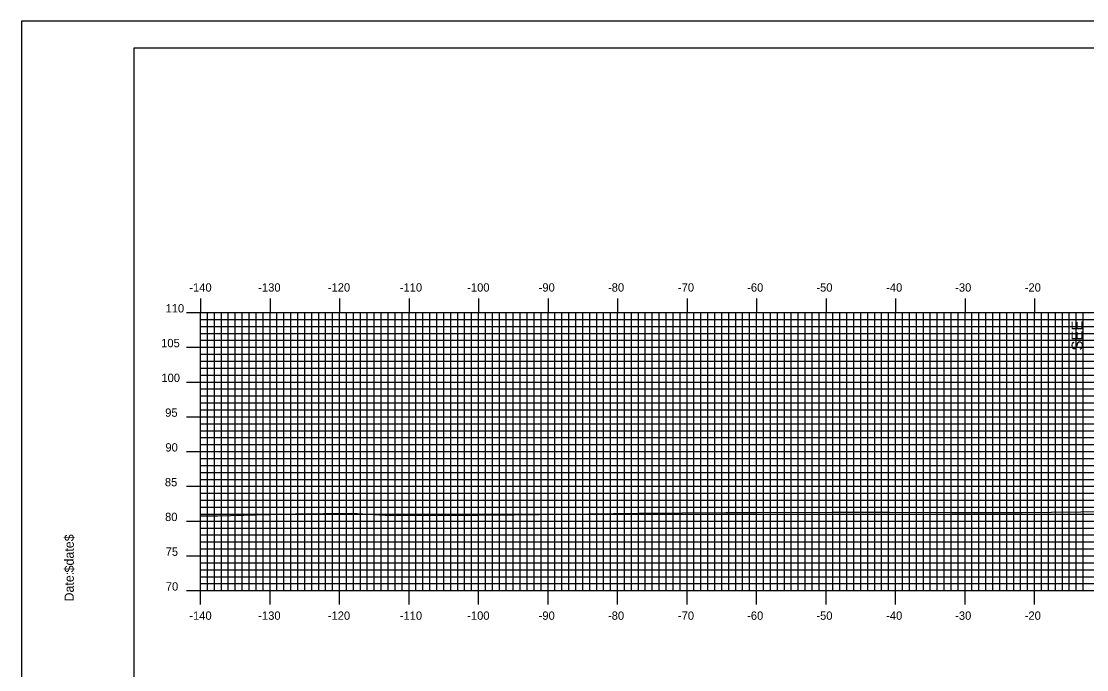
# Model space of a CAD drawing. Extents: x 2846 to 3190, y -1658 to -1438.
# Drawn here: x 2846.4 to 2999.7, y -1531 to -1437.7 of the extents above; entities that cross this region are included whole.
import ezdxf

# ---------------------------------------------------------------- set-up
doc = ezdxf.new("R2010")
doc.units = 0
for name, color, linetype in [('ANNOTATION', 7, 'Continuous'), ('BORDER', 7, 'Continuous'), ('H_V ANNOTATION', 7, 'Continuous'), ('MAJOR', 7, 'Continuous'), ('MINOR', 7, 'Continuous'), ('PLOT BOUNDARY', 7, 'Continuous'), ('S_Roadway_Centerline', 7, 'Continuous')]:
    doc.layers.add(name, color=color, linetype=linetype)

msp = doc.modelspace()

# ---------------------------------------------------------------- linework, layer by layer
at = {"layer": 'BORDER'}
msp.add_lwpolyline([(2862.61, -1651.6), (3182.61, -1651.6), (3182.61, -1441.6), (2862.61, -1441.6)], close=True, dxfattribs=at)
at = {"layer": 'MAJOR'}
for p, q in [((2872.21, -1477.6), (2872.21, -1479.6)), ((2882.21, -1477.6), (2882.21, -1479.6)), ((2892.21, -1477.6), (2892.21, -1479.6)), ((2902.21, -1477.6), (2902.21, -1479.6)), ((2912.21, -1477.6), (2912.21, -1479.6)), ((2922.21, -1477.6), (2922.21, -1479.6)), ((2932.21, -1477.6), (2932.21, -1479.6)), ((2942.21, -1477.6), (2942.21, -1479.6)), ((2952.21, -1477.6), (2952.21, -1479.6)), ((2962.21, -1477.6), (2962.21, -1479.6)), ((2972.21, -1477.6), (2972.21, -1479.6)), ((2982.21, -1477.6), (2982.21, -1479.6)), ((2992.21, -1477.6), (2992.21, -1479.6)), ((2870.21, -1479.6), (2872.21, -1479.6)), ((2872.21, -1479.6), (3152.21, -1479.6)), ((2872.21, -1519.6), (2872.21, -1479.6)), ((2872.21, -1519.6), (2872.21, -1479.6)), ((2872.21, -1479.6), (3152.21, -1479.6)), ((2882.21, -1519.6), (2882.21, -1479.6)), ((2892.21, -1519.6), (2892.21, -1479.6)), ((2902.21, -1519.6), (2902.21, -1479.6)), ((2912.21, -1519.6), (2912.21, -1479.6)), ((2922.21, -1519.6), (2922.21, -1479.6)), ((2932.21, -1519.6), (2932.21, -1479.6)), ((2942.21, -1519.6), (2942.21, -1479.6)), ((2952.21, -1519.6), (2952.21, -1479.6)), ((2962.21, -1519.6), (2962.21, -1479.6)), ((2972.21, -1519.6), (2972.21, -1479.6)), ((2982.21, -1519.6), (2982.21, -1479.6)), ((2992.21, -1519.6), (2992.21, -1479.6)), ((2870.21, -1484.6), (2872.21, -1484.6)), ((2872.21, -1484.6), (3152.21, -1484.6)), ((2870.21, -1489.6), (2872.21, -1489.6)), ((2872.21, -1489.6), (3152.21, -1489.6)), ((2870.21, -1494.6), (2872.21, -1494.6)), ((2872.21, -1494.6), (3152.21, -1494.6)), ((2870.21, -1499.6), (2872.21, -1499.6)), ((2872.21, -1499.6), (3152.21, -1499.6)), ((2870.21, -1504.6), (2872.21, -1504.6)), ((2872.21, -1504.6), (3152.21, -1504.6)), ((2870.21, -1509.6), (2872.21, -1509.6)), ((2872.21, -1509.6), (3152.21, -1509.6)), ((2870.21, -1514.6), (2872.21, -1514.6)), ((2872.21, -1514.6), (3152.21, -1514.6)), ((2870.21, -1519.6), (2872.21, -1519.6)), ((2872.21, -1519.6), (3152.21, -1519.6)), ((2872.21, -1519.6), (3152.21, -1519.6)), ((2872.21, -1521.61), (2872.21, -1519.6)), ((2882.21, -1521.61), (2882.21, -1519.6)), ((2892.21, -1521.61), (2892.21, -1519.6)), ((2902.21, -1521.61), (2902.21, -1519.6)), ((2912.21, -1521.61), (2912.21, -1519.6)), ((2922.21, -1521.61), (2922.21, -1519.6)), ((2932.21, -1521.61), (2932.21, -1519.6)), ((2942.21, -1521.61), (2942.21, -1519.6)), ((2952.21, -1521.61), (2952.21, -1519.6)), ((2962.21, -1521.61), (2962.21, -1519.6)), ((2972.21, -1521.61), (2972.21, -1519.6)), ((2982.21, -1521.61), (2982.21, -1519.6)), ((2992.21, -1521.61), (2992.21, -1519.6))]:
    msp.add_line(p, q, dxfattribs=at)
at = {"layer": 'MINOR'}
for p, q in [((2872.21, -1480.6), (3152.21, -1480.6)), ((2872.21, -1480.6), (2874.22, -1480.6)), ((2873.21, -1519.6), (2873.21, -1479.6)), ((2874.21, -1519.6), (2874.21, -1479.6)), ((2875.21, -1519.6), (2875.21, -1479.6)), ((2876.21, -1519.6), (2876.21, -1479.6)), ((2877.21, -1519.6), (2877.21, -1479.6)), ((2878.21, -1519.6), (2878.21, -1479.6)), ((2879.21, -1519.6), (2879.21, -1479.6)), ((2880.21, -1519.6), (2880.21, -1479.6)), ((2881.21, -1519.6), (2881.21, -1479.6)), ((2883.21, -1519.6), (2883.21, -1479.6)), ((2884.21, -1519.6), (2884.21, -1479.6)), ((2885.21, -1519.6), (2885.21, -1479.6)), ((2886.21, -1519.6), (2886.21, -1479.6)), ((2887.21, -1519.6), (2887.21, -1479.6)), ((2888.21, -1519.6), (2888.21, -1479.6)), ((2889.21, -1519.6), (2889.21, -1479.6)), ((2890.21, -1519.6), (2890.21, -1479.6)), ((2891.21, -1519.6), (2891.21, -1479.6)), ((2893.21, -1519.6), (2893.21, -1479.6)), ((2894.21, -1519.6), (2894.21, -1479.6)), ((2895.21, -1519.6), (2895.21, -1479.6)), ((2896.21, -1519.6), (2896.21, -1479.6)), ((2897.21, -1519.6), (2897.21, -1479.6)), ((2898.21, -1519.6), (2898.21, -1479.6)), ((2899.21, -1519.6), (2899.21, -1479.6)), ((2900.21, -1519.6), (2900.21, -1479.6)), ((2901.21, -1519.6), (2901.21, -1479.6)), ((2903.21, -1519.6), (2903.21, -1479.6)), ((2904.21, -1519.6), (2904.21, -1479.6)), ((2905.21, -1519.6), (2905.21, -1479.6)), ((2906.21, -1519.6), (2906.21, -1479.6)), ((2907.21, -1519.6), (2907.21, -1479.6)), ((2908.21, -1519.6), (2908.21, -1479.6)), ((2909.21, -1519.6), (2909.21, -1479.6)), ((2910.21, -1519.6), (2910.21, -1479.6)), ((2911.21, -1519.6), (2911.21, -1479.6)), ((2913.21, -1519.6), (2913.21, -1479.6)), ((2914.21, -1519.6), (2914.21, -1479.6)), ((2915.21, -1519.6), (2915.21, -1479.6)), ((2916.21, -1519.6), (2916.21, -1479.6)), ((2917.21, -1519.6), (2917.21, -1479.6)), ((2918.21, -1519.6), (2918.21, -1479.6)), ((2919.21, -1519.6), (2919.21, -1479.6)), ((2920.21, -1519.6), (2920.21, -1479.6)), ((2921.21, -1519.6), (2921.21, -1479.6)), ((2923.21, -1519.6), (2923.21, -1479.6)), ((2924.21, -1519.6), (2924.21, -1479.6)), ((2925.21, -1519.6), (2925.21, -1479.6)), ((2926.21, -1519.6), (2926.21, -1479.6)), ((2927.21, -1519.6), (2927.21, -1479.6)), ((2928.21, -1519.6), (2928.21, -1479.6)), ((2929.21, -1519.6), (2929.21, -1479.6)), ((2930.21, -1519.6), (2930.21, -1479.6)), ((2931.21, -1519.6), (2931.21, -1479.6)), ((2933.21, -1519.6), (2933.21, -1479.6)), ((2934.21, -1519.6), (2934.21, -1479.6)), ((2935.21, -1519.6), (2935.21, -1479.6)), ((2936.21, -1519.6), (2936.21, -1479.6)), ((2937.21, -1519.6), (2937.21, -1479.6)), ((2938.21, -1519.6), (2938.21, -1479.6)), ((2939.21, -1519.6), (2939.21, -1479.6)), ((2940.21, -1519.6), (2940.21, -1479.6)), ((2941.21, -1519.6), (2941.21, -1479.6)), ((2943.21, -1519.6), (2943.21, -1479.6)), ((2944.21, -1519.6), (2944.21, -1479.6)), ((2945.21, -1519.6), (2945.21, -1479.6)), ((2946.21, -1519.6), (2946.21, -1479.6)), ((2947.21, -1519.6), (2947.21, -1479.6)), ((2948.21, -1519.6), (2948.21, -1479.6)), ((2949.21, -1519.6), (2949.21, -1479.6)), ((2950.21, -1519.6), (2950.21, -1479.6)), ((2951.21, -1519.6), (2951.21, -1479.6)), ((2953.21, -1519.6), (2953.21, -1479.6)), ((2954.21, -1519.6), (2954.21, -1479.6)), ((2955.21, -1519.6), (2955.21, -1479.6)), ((2956.21, -1519.6), (2956.21, -1479.6)), ((2957.21, -1519.6), (2957.21, -1479.6)), ((2958.21, -1519.6), (2958.21, -1479.6)), ((2959.21, -1519.6), (2959.21, -1479.6)), ((2960.21, -1519.6), (2960.21, -1479.6)), ((2961.21, -1519.6), (2961.21, -1479.6)), ((2963.21, -1519.6), (2963.21, -1479.6)), ((2964.21, -1519.6), (2964.21, -1479.6)), ((2965.21, -1519.6), (2965.21, -1479.6)), ((2966.21, -1519.6), (2966.21, -1479.6)), ((2967.21, -1519.6), (2967.21, -1479.6)), ((2968.21, -1519.6), (2968.21, -1479.6)), ((2969.21, -1519.6), (2969.21, -1479.6)), ((2970.21, -1519.6), (2970.21, -1479.6)), ((2971.21, -1519.6), (2971.21, -1479.6)), ((2973.21, -1519.6), (2973.21, -1479.6)), ((2974.21, -1519.6), (2974.21, -1479.6)), ((2975.21, -1519.6), (2975.21, -1479.6)), ((2976.21, -1519.6), (2976.21, -1479.6)), ((2977.21, -1519.6), (2977.21, -1479.6)), ((2978.21, -1519.6), (2978.21, -1479.6)), ((2979.21, -1519.6), (2979.21, -1479.6)), ((2980.21, -1519.6), (2980.21, -1479.6)), ((2981.21, -1519.6), (2981.21, -1479.6)), ((2983.21, -1519.6), (2983.21, -1479.6)), ((2984.21, -1519.6), (2984.21, -1479.6)), ((2985.21, -1519.6), (2985.21, -1479.6)), ((2986.21, -1519.6), (2986.21, -1479.6)), ((2987.21, -1519.6), (2987.21, -1479.6)), ((2988.21, -1519.6), (2988.21, -1479.6)), ((2989.21, -1519.6), (2989.21, -1479.6)), ((2990.21, -1519.6), (2990.21, -1479.6)), ((2991.21, -1519.6), (2991.21, -1479.6)), ((2993.21, -1519.6), (2993.21, -1479.6)), ((2994.21, -1519.6), (2994.21, -1479.6)), ((2995.21, -1519.6), (2995.21, -1479.6)), ((2996.21, -1519.6), (2996.21, -1479.6)), ((2997.21, -1519.6), (2997.21, -1479.6)), ((2998.21, -1519.6), (2998.21, -1479.6)), ((2999.21, -1519.6), (2999.21, -1479.6)), ((2872.21, -1481.6), (3152.21, -1481.6)), ((2872.21, -1481.6), (2874.22, -1481.6)), ((2872.21, -1482.6), (3152.21, -1482.6)), ((2872.21, -1482.6), (2874.22, -1482.6)), ((2872.21, -1483.6), (3152.21, -1483.6)), ((2872.21, -1483.6), (2874.22, -1483.6)), ((2872.21, -1485.6), (3152.21, -1485.6)), ((2872.21, -1485.6), (2874.22, -1485.6)), ((2872.21, -1486.6), (3152.21, -1486.6)), ((2872.21, -1486.6), (2874.22, -1486.6)), ((2872.21, -1487.6), (3152.21, -1487.6)), ((2872.21, -1487.6), (2874.22, -1487.6)), ((2872.21, -1488.6), (3152.21, -1488.6)), ((2872.21, -1488.6), (2874.22, -1488.6)), ((2872.21, -1490.6), (3152.21, -1490.6)), ((2872.21, -1490.6), (2874.22, -1490.6)), ((2872.21, -1491.6), (3152.21, -1491.6)), ((2872.21, -1491.6), (2874.22, -1491.6)), ((2872.21, -1492.6), (3152.21, -1492.6)), ((2872.21, -1492.6), (2874.22, -1492.6)), ((2872.21, -1493.6), (3152.21, -1493.6)), ((2872.21, -1493.6), (2874.22, -1493.6)), ((2872.21, -1495.6), (3152.21, -1495.6)), ((2872.21, -1495.6), (2874.22, -1495.6)), ((2872.21, -1496.6), (3152.21, -1496.6)), ((2872.21, -1496.6), (2874.22, -1496.6)), ((2872.21, -1497.6), (3152.21, -1497.6)), ((2872.21, -1497.6), (2874.22, -1497.6)), ((2872.21, -1498.6), (3152.21, -1498.6)), ((2872.21, -1498.6), (2874.22, -1498.6)), ((2872.21, -1500.6), (3152.21, -1500.6)), ((2872.21, -1500.6), (2874.22, -1500.6)), ((2872.21, -1501.6), (3152.21, -1501.6)), ((2872.21, -1501.6), (2874.22, -1501.6)), ((2872.21, -1502.6), (3152.21, -1502.6)), ((2872.21, -1502.6), (2874.22, -1502.6)), ((2872.21, -1503.6), (3152.21, -1503.6)), ((2872.21, -1503.6), (2874.22, -1503.6)), ((2872.21, -1505.6), (3152.21, -1505.6)), ((2872.21, -1505.6), (2874.22, -1505.6)), ((2872.21, -1506.6), (3152.21, -1506.6)), ((2872.21, -1506.6), (2874.22, -1506.6)), ((2872.21, -1507.6), (3152.21, -1507.6)), ((2872.21, -1507.6), (2874.22, -1507.6)), ((2872.21, -1508.6), (3152.21, -1508.6)), ((2872.21, -1508.6), (2874.22, -1508.6)), ((2872.21, -1510.6), (3152.21, -1510.6)), ((2872.21, -1510.6), (2874.22, -1510.6)), ((2872.21, -1511.6), (3152.21, -1511.6)), ((2872.21, -1511.6), (2874.22, -1511.6)), ((2872.21, -1512.6), (3152.21, -1512.6)), ((2872.21, -1512.6), (2874.22, -1512.6)), ((2872.21, -1513.6), (3152.21, -1513.6)), ((2872.21, -1513.6), (2874.22, -1513.6)), ((2872.21, -1515.6), (3152.21, -1515.6)), ((2872.21, -1515.6), (2874.22, -1515.6)), ((2872.21, -1516.6), (3152.21, -1516.6)), ((2872.21, -1516.6), (2874.22, -1516.6)), ((2872.21, -1517.6), (3152.21, -1517.6)), ((2872.21, -1517.6), (2874.22, -1517.6)), ((2872.21, -1518.6), (3152.21, -1518.6)), ((2872.21, -1518.6), (2874.22, -1518.6))]:
    msp.add_line(p, q, dxfattribs=at)
at = {"layer": 'PLOT BOUNDARY'}
msp.add_lwpolyline([(2846.43, -1657.72), (3186.43, -1657.72), (3186.43, -1437.72), (2846.43, -1437.72)], close=True, dxfattribs=at)
at = {"layer": 'S_Roadway_Centerline'}
msp.add_lwpolyline([(2872.21, -1508.85), (2874.71, -1508.85), (2885.9, -1508.57), (2893.94, -1508.45), (2899.61, -1508.81), (2912.04, -1508.73), (2917.35, -1508.68), (2935.24, -1508.46), (2947.81, -1508.37), (2952.31, -1508.37), (2963.28, -1508.33), (2971.32, -1508.33), (2980.37, -1508.35), (2990.42, -1508.38), (2998.86, -1508.25), (3009.93, -1508.16)], dxfattribs=at)

# ---------------------------------------------------------------- texts
at = {"layer": 'ANNOTATION'}
msp.add_text('SEE', height=1.6, rotation=90, dxfattribs=at).set_placement((2999.14, -1485.07))
at = {"layer": 'BORDER'}
for s, p in [('$date$', (2853.98, -1516.99)), ('Date:', (2853.98, -1521.17))]:
    msp.add_text(s, height=1.339, rotation=90, dxfattribs=at).set_placement(p)
at = {"layer": 'H_V ANNOTATION'}
for s, p in [('-140', (2870.6, -1476.6)), ('-130', (2880.52, -1476.6)), ('-120', (2890.53, -1476.6)), ('-110', (2900.88, -1476.6)), ('-100', (2910.58, -1476.6)), ('-90', (2920.86, -1476.6)), ('-80', (2930.84, -1476.6)), ('-70', (2940.9, -1476.6)), ('-60', (2950.86, -1476.6)), ('-50', (2960.82, -1476.6)), ('-40', (2970.86, -1476.6)), ('-30', (2980.79, -1476.6)), ('-20', (2990.8, -1476.6)), ('110', (2867.18, -1479.6)), ('105', (2866.55, -1484.6)), ('100', (2866.58, -1489.6)), ('95', (2867.13, -1494.6)), ('90', (2867.16, -1499.6)), ('85', (2867.08, -1504.6)), ('80', (2867.11, -1509.6)), ('75', (2867.19, -1514.6)), ('70', (2867.22, -1519.6)), ('-140', (2870.6, -1523.8)), ('-130', (2880.52, -1523.8)), ('-120', (2890.53, -1523.8)), ('-110', (2900.88, -1523.8)), ('-100', (2910.58, -1523.8)), ('-90', (2920.86, -1523.8)), ('-80', (2930.84, -1523.8)), ('-70', (2940.9, -1523.8)), ('-60', (2950.86, -1523.8)), ('-50', (2960.82, -1523.8)), ('-40', (2970.86, -1523.8)), ('-30', (2980.79, -1523.8)), ('-20', (2990.8, -1523.8))]:
    msp.add_text(s, height=1.2, dxfattribs=at).set_placement(p)
at = {"layer": 'MAJOR'}
msp.add_text('-', height=0.012, dxfattribs=at).set_placement((2872.2, -1519.6))

doc.saveas('drawing.dxf')
